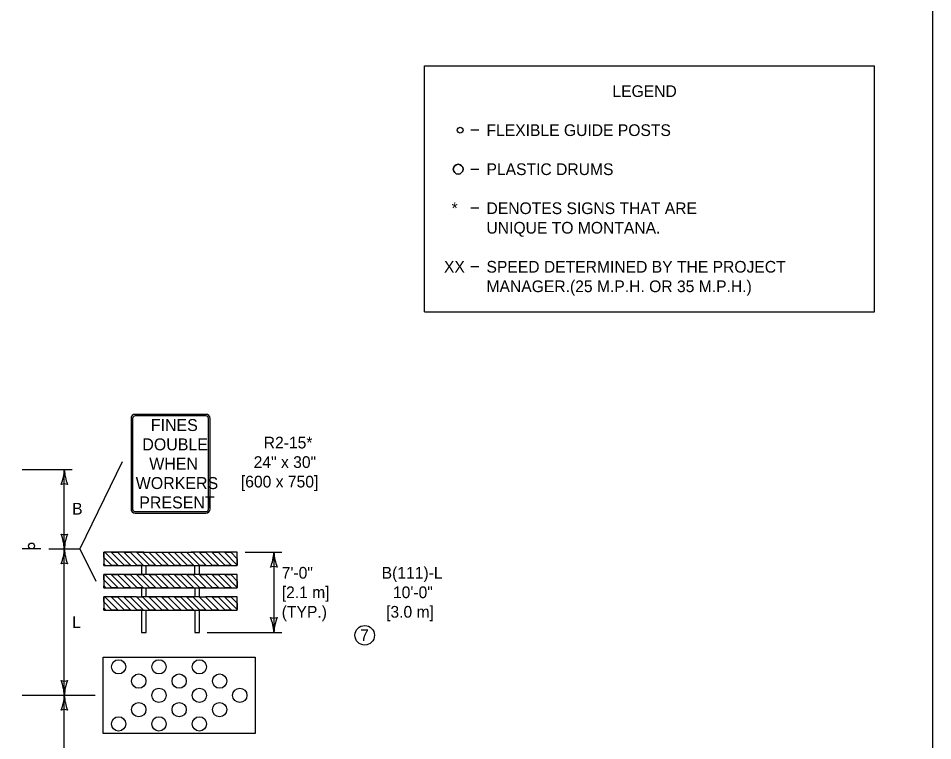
# Model space of a CAD drawing. Extents: x 49991.4 to 50021, y 49987.6 to 50011.4.
# Drawn here: x 50003.928 to 50008.615, y 50003.594 to 50007.296 of the extents above; entities that cross this region are included whole.
import ezdxf

# ---------------------------------------------------------------- set-up
doc = ezdxf.new("R2010")
doc.units = 0
for name, color, linetype in [('Level 1', 7, 'Continuous'), ('Level 2', 7, 'Continuous'), ('Level 3', 7, 'Continuous')]:
    doc.layers.add(name, color=color, linetype=linetype)

msp = doc.modelspace()

# ---------------------------------------------------------------- linework, layer by layer
at = {"layer": 'Level 1'}
for p, q in [((50006.0096, 50005.7924), (50006.0096, 50007.0524)), ((50008.3163, 50005.7924), (50008.3163, 50007.0524)), ((50006.2874, 50006.7224), (50006.2474, 50006.7224)), ((50006.2474, 50006.5224), (50006.2874, 50006.5224)), ((50006.2874, 50006.3224), (50006.2474, 50006.3224)), ((50006.2874, 50006.0224), (50006.2474, 50006.0224)), ((50006.0096, 50005.7924), (50008.3163, 50005.7924)), ((50004.8893, 50005.2664), (50004.5265, 50005.2664)), ((50004.5054, 50005.2453), (50004.5054, 50004.7811)), ((50004.5138, 50005.2453), (50004.5138, 50004.7811)), ((50004.8893, 50005.258), (50004.5265, 50005.258)), ((50004.902, 50004.7811), (50004.902, 50005.2453)), ((50004.9104, 50004.7811), (50004.9104, 50005.2453)), ((50004.5265, 50004.7685), (50004.8893, 50004.7685)), ((50004.5265, 50004.76), (50004.8893, 50004.76)), ((50004.0436, 50004.5767), (50003.9476, 50004.5767)), ((50004.4399, 50004.4914), (50004.3715, 50004.5598)), ((50004.3715, 50004.5598), (50004.4399, 50004.4914)), ((50004.4722, 50004.4914), (50004.4038, 50004.5598)), ((50004.4722, 50004.4914), (50004.4038, 50004.5598)), ((50004.5044, 50004.4914), (50004.436, 50004.5598)), ((50004.436, 50004.5598), (50004.5044, 50004.4914)), ((50004.5366, 50004.4914), (50004.4682, 50004.5598)), ((50004.5366, 50004.4914), (50004.4682, 50004.5598)), ((50004.5689, 50004.4914), (50004.5005, 50004.5598)), ((50004.5005, 50004.5598), (50004.5689, 50004.4914)), ((50004.6012, 50004.4914), (50004.5328, 50004.5598)), ((50004.6334, 50004.4914), (50004.565, 50004.5598)), ((50004.565, 50004.5598), (50004.6049, 50004.5598)), ((50004.5854, 50004.5598), (50004.8304, 50004.5598)), ((50004.6656, 50004.4914), (50004.5972, 50004.5598)), ((50004.6978, 50004.4914), (50004.6294, 50004.5598)), ((50004.73, 50004.4914), (50004.6616, 50004.5598)), ((50004.7622, 50004.4914), (50004.6938, 50004.5598)), ((50004.7944, 50004.4914), (50004.726, 50004.5598)), ((50004.8266, 50004.4914), (50004.7582, 50004.5598)), ((50004.859, 50004.4914), (50004.7906, 50004.5598)), ((50004.8447, 50004.5598), (50004.8134, 50004.5598)), ((50004.8912, 50004.4914), (50004.8229, 50004.5598)), ((50004.9235, 50004.4914), (50004.8551, 50004.5598)), ((50004.9235, 50004.4914), (50004.8551, 50004.5598)), ((50004.9557, 50004.4914), (50004.8873, 50004.5598)), ((50004.8873, 50004.5598), (50004.9557, 50004.4914)), ((50004.988, 50004.4914), (50004.9196, 50004.5598)), ((50004.988, 50004.4914), (50004.9196, 50004.5598)), ((50005.0202, 50004.4914), (50004.9518, 50004.5598)), ((50004.9518, 50004.5598), (50005.0202, 50004.4914)), ((50005.0499, 50004.4939), (50004.984, 50004.5598)), ((50005.0499, 50004.4939), (50004.984, 50004.5598)), ((50005.0499, 50004.5262), (50005.0163, 50004.5598)), ((50005.0163, 50004.5598), (50005.0499, 50004.5262)), ((50004.4077, 50004.4914), (50004.3659, 50004.5331)), ((50004.4077, 50004.4914), (50004.3659, 50004.5331)), ((50004.3755, 50004.4914), (50004.3659, 50004.5009)), ((50004.3659, 50004.5009), (50004.3755, 50004.4914)), ((50004.5825, 50004.4458), (50004.5825, 50004.4914)), ((50004.8333, 50004.4458), (50004.8333, 50004.4914)), ((50004.4077, 50004.3774), (50004.3659, 50004.4192)), ((50004.4077, 50004.3774), (50004.3659, 50004.4192)), ((50004.4399, 50004.3774), (50004.3715, 50004.4458)), ((50004.3715, 50004.4458), (50004.4399, 50004.3774)), ((50004.4722, 50004.3774), (50004.4038, 50004.4458)), ((50004.4722, 50004.3774), (50004.4038, 50004.4458)), ((50004.5044, 50004.3774), (50004.436, 50004.4458)), ((50004.436, 50004.4458), (50004.5044, 50004.3774)), ((50004.5366, 50004.3774), (50004.4682, 50004.4458)), ((50004.5366, 50004.3774), (50004.4682, 50004.4458)), ((50004.5689, 50004.3774), (50004.5005, 50004.4458)), ((50004.5005, 50004.4458), (50004.5689, 50004.3774)), ((50004.5711, 50004.4075), (50004.5328, 50004.4458)), ((50004.5711, 50004.4397), (50004.565, 50004.4458)), ((50004.6334, 50004.3774), (50004.5711, 50004.4397)), ((50004.6656, 50004.3774), (50004.5972, 50004.4458)), ((50004.6978, 50004.3774), (50004.6294, 50004.4458)), ((50004.7301, 50004.3774), (50004.6617, 50004.4458)), ((50004.7623, 50004.3774), (50004.6939, 50004.4458)), ((50004.7945, 50004.3774), (50004.7261, 50004.4458)), ((50004.8268, 50004.3774), (50004.7584, 50004.4458)), ((50004.859, 50004.3774), (50004.7906, 50004.4458)), ((50004.8912, 50004.3774), (50004.8229, 50004.4458)), ((50004.9235, 50004.3774), (50004.8551, 50004.4458)), ((50004.9235, 50004.3774), (50004.8551, 50004.4458)), ((50004.9557, 50004.3774), (50004.8873, 50004.4458)), ((50004.8873, 50004.4458), (50004.9557, 50004.3774)), ((50004.988, 50004.3774), (50004.9196, 50004.4458)), ((50004.988, 50004.3774), (50004.9196, 50004.4458)), ((50005.0202, 50004.3774), (50004.9518, 50004.4458)), ((50004.9518, 50004.4458), (50005.0202, 50004.3774)), ((50005.0499, 50004.38), (50004.984, 50004.4458)), ((50005.0499, 50004.38), (50004.984, 50004.4458)), ((50005.0499, 50004.4122), (50005.0163, 50004.4458)), ((50005.0163, 50004.4458), (50005.0499, 50004.4122)), ((50004.3755, 50004.3774), (50004.3659, 50004.387)), ((50004.3659, 50004.387), (50004.3755, 50004.3774)), ((50004.6012, 50004.3774), (50004.5711, 50004.4075)), ((50004.4399, 50004.2635), (50004.3715, 50004.3319)), ((50004.3715, 50004.3319), (50004.4399, 50004.2635)), ((50004.4722, 50004.2635), (50004.4038, 50004.3319)), ((50004.4722, 50004.2635), (50004.4038, 50004.3319)), ((50004.5044, 50004.2635), (50004.436, 50004.3319)), ((50004.436, 50004.3319), (50004.5044, 50004.2635)), ((50004.5366, 50004.2635), (50004.4682, 50004.3319)), ((50004.5366, 50004.2635), (50004.4682, 50004.3319)), ((50004.5689, 50004.2635), (50004.5005, 50004.3319)), ((50004.5005, 50004.3319), (50004.5689, 50004.2635)), ((50004.6012, 50004.2635), (50004.5328, 50004.3319)), ((50004.6012, 50004.2635), (50004.5328, 50004.3319)), ((50004.6334, 50004.2635), (50004.565, 50004.3319)), ((50004.565, 50004.3319), (50004.6334, 50004.2635)), ((50004.6656, 50004.2635), (50004.5972, 50004.3319)), ((50004.6656, 50004.2635), (50004.5972, 50004.3319)), ((50004.6978, 50004.2635), (50004.6294, 50004.3319)), ((50004.6294, 50004.3319), (50004.6978, 50004.2635)), ((50004.7301, 50004.2635), (50004.6617, 50004.3319)), ((50004.7301, 50004.2635), (50004.6617, 50004.3319)), ((50004.7623, 50004.2635), (50004.6939, 50004.3319)), ((50004.6939, 50004.3319), (50004.7623, 50004.2635)), ((50004.7945, 50004.2635), (50004.7261, 50004.3319)), ((50004.7945, 50004.2635), (50004.7261, 50004.3319)), ((50004.8268, 50004.2635), (50004.7584, 50004.3319)), ((50004.7584, 50004.3319), (50004.8268, 50004.2635)), ((50004.859, 50004.2635), (50004.7906, 50004.3319)), ((50004.859, 50004.2635), (50004.7906, 50004.3319)), ((50004.8912, 50004.2635), (50004.8229, 50004.3319)), ((50004.8229, 50004.3319), (50004.8912, 50004.2635)), ((50004.9235, 50004.2635), (50004.8551, 50004.3319)), ((50004.9235, 50004.2635), (50004.8551, 50004.3319)), ((50004.9557, 50004.2635), (50004.8873, 50004.3319)), ((50004.8873, 50004.3319), (50004.9557, 50004.2635)), ((50004.988, 50004.2635), (50004.9196, 50004.3319)), ((50004.988, 50004.2635), (50004.9196, 50004.3319)), ((50005.0202, 50004.2635), (50004.9518, 50004.3319)), ((50004.9518, 50004.3319), (50005.0202, 50004.2635)), ((50005.0499, 50004.266), (50004.984, 50004.3319)), ((50005.0499, 50004.266), (50004.984, 50004.3319)), ((50005.0499, 50004.2983), (50005.0163, 50004.3319)), ((50005.0163, 50004.3319), (50005.0499, 50004.2983)), ((50004.4077, 50004.2635), (50004.3659, 50004.3052)), ((50004.4077, 50004.2635), (50004.3659, 50004.3052)), ((50004.3755, 50004.2635), (50004.3659, 50004.273)), ((50004.3659, 50004.273), (50004.3755, 50004.2635))]:
    msp.add_line(p, q, dxfattribs=at)
for points in [[(50008.6146, 50011.2628), (50000.3356, 50011.2628), (50000.3356, 50000.0624), (50008.6146, 50000.0624)], [(50005.142, 50003.6317), (50004.3623, 50003.6317), (50004.3623, 50004.0217), (50005.142, 50004.0217)], [(50005.142, 50003.6317), (50004.3623, 50003.6317), (50004.3623, 50004.0217), (50005.142, 50004.0217)]]:
    msp.add_lwpolyline(points, close=True, dxfattribs=at)
for points in [[(50006.0096, 50007.0524), (50008.3163, 50007.0524)], [(50004.5711, 50004.5598), (50004.3659, 50004.5598), (50004.3659, 50004.4914), (50004.5711, 50004.4914)], [(50004.3659, 50004.5331), (50004.3659, 50004.5598), (50004.3715, 50004.5598)], [(50004.4038, 50004.5598), (50004.436, 50004.5598)], [(50004.4682, 50004.5598), (50004.5005, 50004.5598)], [(50004.6334, 50004.4914), (50004.6012, 50004.4914), (50004.5328, 50004.5598), (50004.565, 50004.5598), (50004.6334, 50004.4914)], [(50004.5711, 50004.4914), (50005.0499, 50004.4914), (50005.0499, 50004.5598), (50004.8447, 50004.5598)], [(50004.5972, 50004.5598), (50004.6049, 50004.5598), (50004.6294, 50004.5598), (50004.6978, 50004.4914), (50004.6656, 50004.4914), (50004.5972, 50004.5598)], [(50004.6616, 50004.5598), (50004.6938, 50004.5598), (50004.7622, 50004.4914), (50004.73, 50004.4914), (50004.6616, 50004.5598)], [(50004.726, 50004.5598), (50004.7582, 50004.5598), (50004.8266, 50004.4914), (50004.7944, 50004.4914), (50004.726, 50004.5598)], [(50004.7906, 50004.5598), (50004.8134, 50004.5598), (50004.8229, 50004.5598), (50004.8912, 50004.4914), (50004.859, 50004.4914), (50004.7906, 50004.5598)], [(50004.8551, 50004.5598), (50004.8873, 50004.5598)], [(50004.9196, 50004.5598), (50004.9518, 50004.5598)], [(50004.984, 50004.5598), (50005.0163, 50004.5598)], [(50005.0499, 50004.5262), (50005.0499, 50004.4939)], [(50004.3755, 50004.4914), (50004.3659, 50004.4914), (50004.3659, 50004.5009)], [(50004.4399, 50004.4914), (50004.4077, 50004.4914)], [(50004.5044, 50004.4914), (50004.4722, 50004.4914)], [(50004.5689, 50004.4914), (50004.5366, 50004.4914)], [(50004.5597, 50004.4914), (50004.5597, 50004.4458)], [(50004.8561, 50004.4458), (50004.8561, 50004.4914)], [(50004.9557, 50004.4914), (50004.9235, 50004.4914)], [(50005.0202, 50004.4914), (50004.988, 50004.4914)], [(50004.5711, 50004.4458), (50004.3659, 50004.4458), (50004.3659, 50004.3774), (50005.0499, 50004.3774), (50005.0499, 50004.4458), (50004.5711, 50004.4458)], [(50004.3659, 50004.4192), (50004.3659, 50004.4458), (50004.3715, 50004.4458)], [(50004.4038, 50004.4458), (50004.436, 50004.4458)], [(50004.4682, 50004.4458), (50004.5005, 50004.4458)], [(50004.6334, 50004.3774), (50004.6012, 50004.3774), (50004.5711, 50004.4075), (50004.5328, 50004.4458), (50004.5597, 50004.4458), (50004.565, 50004.4458), (50004.5711, 50004.4397), (50004.6334, 50004.3774)], [(50004.5972, 50004.4458), (50004.6294, 50004.4458), (50004.6978, 50004.3774), (50004.6656, 50004.3774), (50004.5972, 50004.4458)], [(50004.6617, 50004.4458), (50004.6939, 50004.4458), (50004.7623, 50004.3774), (50004.7301, 50004.3774), (50004.6617, 50004.4458)], [(50004.7261, 50004.4458), (50004.7584, 50004.4458), (50004.8268, 50004.3774), (50004.7945, 50004.3774), (50004.7261, 50004.4458)], [(50004.7906, 50004.4458), (50004.8229, 50004.4458), (50004.8912, 50004.3774), (50004.859, 50004.3774), (50004.7906, 50004.4458)], [(50004.8551, 50004.4458), (50004.8873, 50004.4458)], [(50004.9196, 50004.4458), (50004.9518, 50004.4458)], [(50004.984, 50004.4458), (50005.0163, 50004.4458)], [(50004.3755, 50004.3774), (50004.3659, 50004.3774), (50004.3659, 50004.387)], [(50004.4399, 50004.3774), (50004.4077, 50004.3774)], [(50004.5044, 50004.3774), (50004.4722, 50004.3774)], [(50004.5689, 50004.3774), (50004.5366, 50004.3774)], [(50004.5597, 50004.3774), (50004.5597, 50004.3319)], [(50004.5825, 50004.3319), (50004.5825, 50004.3774)], [(50004.8333, 50004.3774), (50004.8333, 50004.3319)], [(50004.8561, 50004.3319), (50004.8561, 50004.3774)], [(50004.9557, 50004.3774), (50004.9235, 50004.3774)], [(50005.0202, 50004.3774), (50004.988, 50004.3774)], [(50005.0499, 50004.4122), (50005.0499, 50004.38)], [(50004.3659, 50004.3052), (50004.3659, 50004.3319), (50004.3715, 50004.3319)], [(50004.5328, 50004.3319), (50004.3659, 50004.3319), (50004.3659, 50004.2635), (50005.0499, 50004.2635), (50005.0499, 50004.3319), (50004.8873, 50004.3319)], [(50004.4038, 50004.3319), (50004.436, 50004.3319)], [(50004.4682, 50004.3319), (50004.5005, 50004.3319)], [(50004.5328, 50004.3319), (50004.565, 50004.3319)], [(50004.8551, 50004.3319), (50004.565, 50004.3319)], [(50004.5972, 50004.3319), (50004.6294, 50004.3319)], [(50004.6617, 50004.3319), (50004.6939, 50004.3319)], [(50004.7261, 50004.3319), (50004.7584, 50004.3319)], [(50004.7906, 50004.3319), (50004.8229, 50004.3319)], [(50004.8551, 50004.3319), (50004.8873, 50004.3319)], [(50004.9196, 50004.3319), (50004.9518, 50004.3319)], [(50004.984, 50004.3319), (50005.0163, 50004.3319)], [(50005.0499, 50004.2983), (50005.0499, 50004.266)], [(50004.3755, 50004.2635), (50004.3659, 50004.2635), (50004.3659, 50004.273)], [(50004.4399, 50004.2635), (50004.4077, 50004.2635)], [(50004.5044, 50004.2635), (50004.4722, 50004.2635)], [(50004.5689, 50004.2635), (50004.5366, 50004.2635)], [(50004.5597, 50004.2634), (50004.5597, 50004.1494), (50004.5825, 50004.1494), (50004.5825, 50004.2634)], [(50004.6334, 50004.2635), (50004.6012, 50004.2635)], [(50004.6978, 50004.2635), (50004.6656, 50004.2635)], [(50004.7623, 50004.2635), (50004.7301, 50004.2635)], [(50004.8268, 50004.2635), (50004.7945, 50004.2635)], [(50004.8333, 50004.2634), (50004.8333, 50004.1494), (50004.8561, 50004.1494), (50004.8561, 50004.2634)], [(50004.8912, 50004.2635), (50004.859, 50004.2635)], [(50004.9557, 50004.2635), (50004.9235, 50004.2635)], [(50005.0202, 50004.2635), (50004.988, 50004.2635)]]:
    msp.add_lwpolyline(points, dxfattribs=at)
for centre, radius in [((50006.1924, 50006.7224), 0.015), ((50006.1824, 50006.5224), 0.025), ((50003.9956, 50004.5919), 0.0152), ((50004.4417, 50003.9727), 0.0366), ((50004.4417, 50003.9727), 0.0366), ((50004.6488, 50003.9727), 0.0366), ((50004.6488, 50003.9727), 0.0366), ((50004.8559, 50003.9727), 0.0366), ((50004.8559, 50003.9727), 0.0366), ((50004.5452, 50003.8996), 0.0366), ((50004.5452, 50003.8996), 0.0366), ((50004.7523, 50003.8996), 0.0366), ((50004.7523, 50003.8996), 0.0366), ((50004.9595, 50003.8996), 0.0366), ((50004.9595, 50003.8996), 0.0366), ((50004.6488, 50003.8265), 0.0366), ((50004.6488, 50003.8265), 0.0366), ((50004.8559, 50003.8265), 0.0366), ((50004.8559, 50003.8265), 0.0366), ((50005.063, 50003.8265), 0.0366), ((50005.063, 50003.8265), 0.0366), ((50004.5452, 50003.7534), 0.0366), ((50004.5452, 50003.7534), 0.0366), ((50004.7523, 50003.7534), 0.0366), ((50004.7523, 50003.7534), 0.0366), ((50004.9595, 50003.7534), 0.0366), ((50004.9595, 50003.7534), 0.0366), ((50004.4417, 50003.6803), 0.0366), ((50004.4417, 50003.6803), 0.0366), ((50004.6488, 50003.6803), 0.0366), ((50004.6488, 50003.6803), 0.0366), ((50004.8559, 50003.6803), 0.0366), ((50004.8559, 50003.6803), 0.0366)]:
    msp.add_circle(centre, radius, dxfattribs=at)
for centre, radius, start, end in [((50006.1824, 50006.5224), 0.025, 360, 180), ((50006.1824, 50006.5224), 0.025, 180, 0), ((50004.5265, 50005.2453), 0.0211, 90, 180), ((50004.8894, 50005.2453), 0.0211, 360, 90), ((50004.5265, 50005.2453), 0.0127, 90, 180), ((50004.8894, 50005.2453), 0.0127, 360, 90), ((50004.5265, 50004.7811), 0.0211, 180, 270), ((50004.5265, 50004.7811), 0.0127, 180, 270), ((50004.8894, 50004.7811), 0.0211, 270, 360), ((50004.8894, 50004.7811), 0.0127, 270, 360)]:
    msp.add_arc(centre, radius, start, end, dxfattribs=at)
at = {"layer": 'Level 2'}
msp.add_circle((50005.7032, 50004.1345), 0.0501, dxfattribs=at)
at = {"layer": 'Level 3'}
for p, q in [((50003.9476, 50004.9833), (50004.2036, 50004.9833)), ((50004.1636, 50004.5826), (50004.1636, 50004.9833)), ((50004.4608, 50005.0237), (50004.2436, 50004.5767)), ((50004.0836, 50004.5767), (50004.2436, 50004.5767)), ((50004.1636, 50003.8267), (50004.1636, 50004.5767)), ((50004.2436, 50004.5767), (50004.3259, 50004.4116)), ((50005.0899, 50004.5598), (50005.2679, 50004.5598)), ((50005.2379, 50004.5598), (50005.2379, 50004.1494)), ((50005.2379, 50004.5598), (50005.2779, 50004.5598)), ((50004.8961, 50004.1494), (50005.2779, 50004.1494)), ((50003.9476, 50003.8267), (50004.3223, 50003.8267)), ((50004.1636, 50003.2267), (50004.1636, 50003.8267))]:
    msp.add_line(p, q, dxfattribs=at)
for centre, radius, start, end in [((50003.9415, 50004.9925), 0.2223, 337.456, 357.6395), ((50004.3963, 50004.9948), 0.233, 182.8273, 202.0772), ((50004.1636, 50004.8551), 0.0548, 72.1388, 107.8612), ((50004.1636, 50004.7049), 0.0548, 252.1388, 287.8612), ((50003.9309, 50004.5652), 0.233, 2.8273, 22.0772), ((50004.3858, 50004.5675), 0.2223, 157.456, 177.6395), ((50003.9415, 50004.5859), 0.2223, 337.456, 357.6395), ((50004.3963, 50004.5882), 0.233, 182.8273, 202.0772), ((50005.0158, 50004.5689), 0.2223, 337.456, 357.6395), ((50005.4706, 50004.5712), 0.233, 182.8273, 202.0772), ((50004.1636, 50004.4485), 0.0548, 72.1388, 107.8612), ((50005.2379, 50004.4315), 0.0548, 72.1388, 107.8612), ((50005.2379, 50004.2776), 0.0548, 252.1388, 287.8612), ((50005.0052, 50004.1379), 0.233, 2.8273, 22.0772), ((50005.46, 50004.1403), 0.2223, 157.456, 177.6395), ((50004.1636, 50003.9549), 0.0548, 252.1388, 287.8612), ((50003.9309, 50003.8152), 0.233, 2.8273, 22.0772), ((50004.3858, 50003.8175), 0.2223, 157.456, 177.6395), ((50003.9415, 50003.8359), 0.2223, 337.456, 357.6395), ((50004.3963, 50003.8382), 0.233, 182.8273, 202.0772), ((50004.1636, 50003.6985), 0.0548, 72.1388, 107.8612)]:
    msp.add_arc(centre, radius, start, end, dxfattribs=at)

# ---------------------------------------------------------------- texts
at = {"layer": 'Level 1'}
for s, p in [('FINES', (50004.6069, 50005.181)), ('DOUBLE', (50004.5634, 50005.0819)), ('WHEN', (50004.5989, 50004.9827)), ('WORKERS', (50004.5295, 50004.8836)), ('PRESENT', (50004.5476, 50004.7844))]:
    msp.add_text(s, height=0.06118, dxfattribs=at).set_placement(p)
at = {"layer": 'Level 2'}
for s, height, p in [('LEGEND', 0.06, (50006.9728, 50006.8924)), ('FLEXIBLE GUIDE POSTS', 0.06, (50006.3274, 50006.6924)), ('PLASTIC DRUMS', 0.06, (50006.3274, 50006.4924)), ('*', 0.0601, (50006.1487, 50006.2923)), ('DENOTES SIGNS THAT ARE', 0.06, (50006.3274, 50006.2924)), ('UNIQUE TO MONTANA.', 0.06, (50006.3274, 50006.1924)), ('XX', 0.06, (50006.1096, 50005.9924)), ('SPEED DETERMINED BY THE PROJECT', 0.06, (50006.3274, 50005.9924)), ('MANAGER.(25 M.P.H. OR 35 M.P.H.)', 0.06, (50006.3274, 50005.8924)), ('R2-15*', 0.06, (50005.1856, 50005.0917)), ('24" x 30"', 0.06, (50005.1341, 50004.9917)), ('[600 x 750]', 0.06, (50005.0685, 50004.8917)), ('B', 0.06, (50004.2036, 50004.7529)), ('7\'-0"', 0.06, (50005.2779, 50004.4246)), ('B(111)-L', 0.06, (50005.7902, 50004.4246)), ('[2.1 m]', 0.06, (50005.2779, 50004.3246)), ('10\'-0"', 0.06, (50005.848, 50004.3246)), ('(TYP.)', 0.06, (50005.2779, 50004.2246)), ('[3.0 m]', 0.06, (50005.8128, 50004.2246)), ('L', 0.06, (50004.2036, 50004.1717)), ('7', 0.06, (50005.6794, 50004.1045))]:
    msp.add_text(s, height=height, dxfattribs=at).set_placement(p)

doc.saveas('drawing.dxf')
